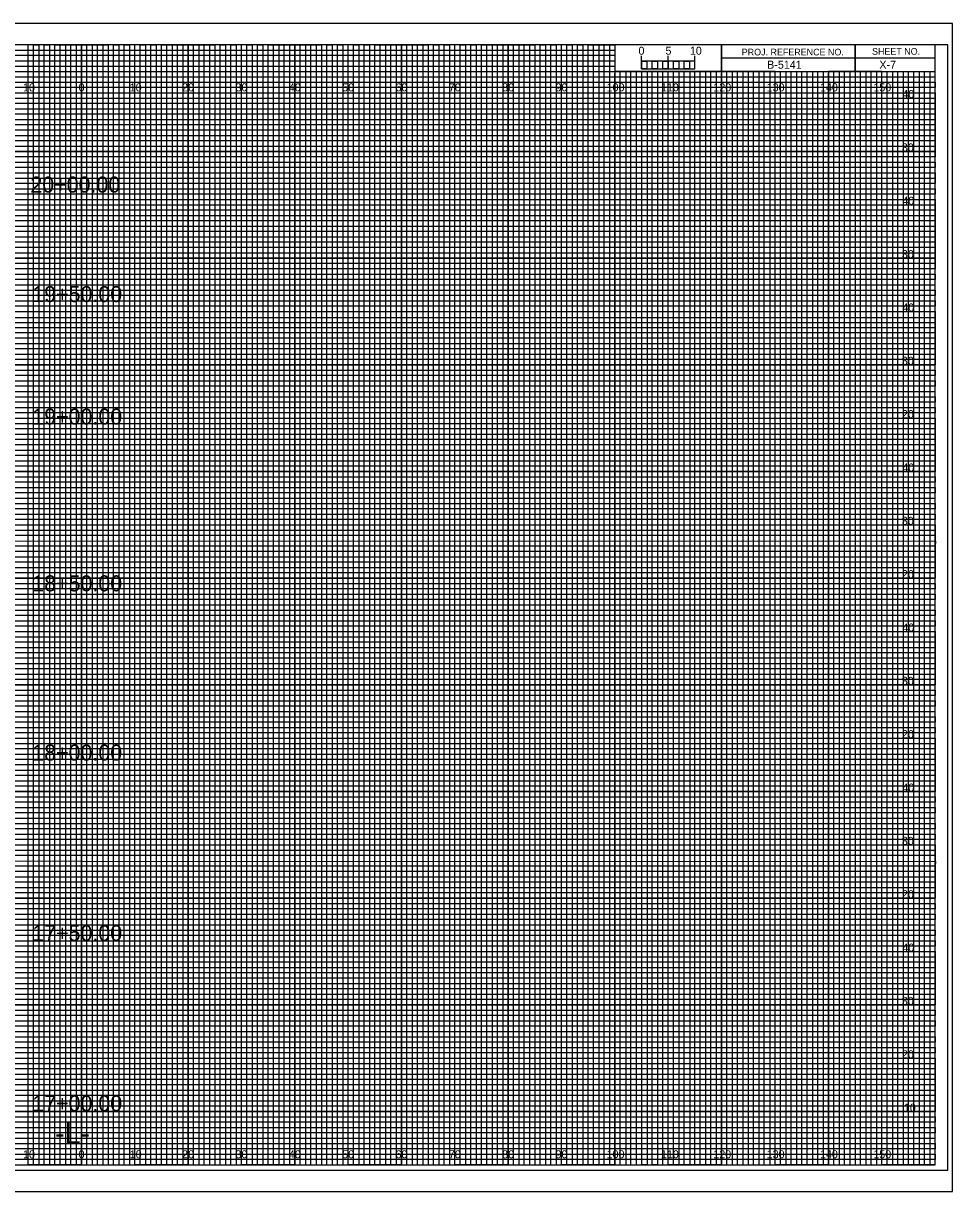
# Model space of a CAD drawing. Extents: x -13 to 323, y 435 to 654.
# Drawn here: x 149.1 to 323.3, y 435 to 654 of the extents above; entities that cross this region are included whole.
import ezdxf

# ---------------------------------------------------------------- set-up
doc = ezdxf.new("R2010")
doc.units = 0
for name, color, linetype in [('Exist Cross Section Cell', 7, 'Continuous'), ('Exist XS Center Line Elevation Label', 7, 'Continuous'), ('Exist XS Ground Line', 7, 'Continuous'), ('Prop XS DDE Slope Text', 7, 'Continuous'), ('Prop XS Earthwork Shape', 7, 'Continuous'), ('Prop XS EOT Tick Mark', 7, 'Continuous'), ('Prop XS Finish Grade', 7, 'Continuous'), ('Prop XS Finish Grade Earthwork', 7, 'Continuous'), ('Prop XS Finish Grade Paved Shoulder', 7, 'Continuous'), ('Prop XS Finish Grade Pavement', 7, 'Continuous'), ('Prop XS Label Text', 7, 'Continuous'), ('Prop XS Pvmt Edge Slope', 7, 'Continuous'), ('Prop XS SE Text', 7, 'Continuous'), ('Prop XS Side Slope Text', 7, 'Continuous'), ('Prop XS Subgrade Earthwork', 7, 'Continuous'), ('Sheet DOT Grid CELL', 7, 'Continuous'), ('Sheet Plot Border Inside CELL', 7, 'Continuous')]:
    doc.layers.add(name, color=color, linetype=linetype)

msp = doc.modelspace()

# ---------------------------------------------------------------- linework, layer by layer
at = {"layer": 'Exist XS Center Line Elevation Label'}
for points in [[(145, 440), (155, 440), (155, 650), (165, 650), (165, 440), (175, 440), (175, 650), (185, 650), (185, 440), (195, 440), (195, 650), (205, 650), (205, 440), (215, 440), (215, 650), (225, 650), (225, 440), (235, 440), (235, 650), (245, 650), (245, 440), (255, 440), (255, 650), (259.93, 650), (260, 650), (260, 645), (264.99, 645), (264.99, 440), (275, 440), (275, 645), (285, 645), (285, 440), (295, 440), (295, 645), (305, 645), (305, 440), (315, 440), (315, 645)], [(0, 645), (275, 645)], [(0, 625), (320, 625), (320, 635), (0, 635)], [(0, 605), (320, 605), (320, 615), (0, 615)], [(0, 585), (320, 585), (320, 595), (0, 595)], [(0, 565), (320, 565), (320, 575), (0, 575)], [(0, 545), (320, 545), (320, 555), (0, 555)], [(0, 525), (320, 525), (320, 535), (0, 535)], [(0, 505), (320, 505), (320, 515), (0, 515)], [(0, 485), (320, 485), (320, 495), (0, 495)], [(0, 465), (320, 465), (320, 475), (0, 475)], [(0, 445), (320, 445), (320, 455), (0, 455)]]:
    msp.add_lwpolyline(points, dxfattribs=at)
at = {"layer": 'Exist XS Ground Line'}
for p, q in [((150, 650), (140, 650)), ((150, 440), (150, 650)), ((170, 650), (160, 650)), ((160, 650), (160, 440)), ((170, 440), (170, 650)), ((190, 650), (180, 650)), ((180, 650), (180, 440)), ((190, 440), (190, 650)), ((210, 650), (200, 650)), ((200, 650), (200, 440)), ((210, 440), (210, 650)), ((230, 650), (220, 650)), ((220, 650), (220, 440)), ((230, 440), (230, 650)), ((250, 650), (240, 650)), ((240, 650), (240, 440)), ((250, 440), (250, 650)), ((260, 650), (260, 440)), ((270, 440), (270, 645)), ((290, 645), (280, 645)), ((280, 645), (280, 440)), ((290, 440), (290, 645)), ((310, 645), (300, 645)), ((300, 645), (300, 440)), ((310, 440), (310, 645)), ((160, 440), (150, 440)), ((180, 440), (170, 440)), ((200, 440), (190, 440)), ((220, 440), (210, 440)), ((240, 440), (230, 440)), ((260, 440), (250, 440)), ((280, 440), (270, 440)), ((300, 440), (290, 440)), ((320, 440), (310, 440)), ((320, 440), (320, 440))]:
    msp.add_line(p, q, dxfattribs=at)
for points in [[(0, 640), (320, 640), (320, 630), (0, 630)], [(0, 620), (320, 620), (320, 610), (0, 610)], [(0, 600), (320, 600), (320, 590), (0, 590)], [(0, 580), (320, 580), (320, 570), (0, 570)], [(0, 560), (320, 560), (320, 550), (0, 550)], [(0, 540), (320, 540), (320, 530), (0, 530)], [(0, 520), (320, 520), (320, 510), (0, 510)], [(0, 500), (320, 500), (320, 490), (0, 490)], [(0, 480), (320, 480), (320, 470), (0, 470)], [(0, 460), (320, 460), (320, 450), (0, 450)]]:
    msp.add_lwpolyline(points, dxfattribs=at)
at = {"layer": 'Prop XS DDE Slope Text'}
msp.add_lwpolyline([(-13.4, 435), (323.3, 435), (323.3, 654), (-13.4, 654)], close=True, dxfattribs=at)
at = {"layer": 'Prop XS Earthwork Shape'}
for p, q in [((0, 649), (260, 649)), ((260, 649), (260, 647.98)), ((260, 647.98), (0, 647.98)), ((0, 647), (260, 647)), ((260, 647), (260, 645.89)), ((260, 645.89), (0, 645.89)), ((0, 644), (320, 644))]:
    msp.add_line(p, q, dxfattribs=at)
for points in [[(0, 643), (270, 643), (320, 643), (320, 642), (0, 642)], [(0, 641), (320, 641), (320, 639), (0, 639)], [(0, 638), (320, 638), (320, 637), (0, 636.98)], [(0, 636), (320, 636), (320, 634), (0, 634)], [(0, 633), (320, 633), (320, 632), (0, 632)], [(0, 631), (320, 631), (320, 629), (0, 629)], [(0, 628), (320, 628), (320, 627), (0, 627)], [(0, 626), (320, 626), (320, 624), (0, 624)], [(0, 623), (320, 623), (320, 622), (0, 622)], [(0, 621), (320, 621), (320, 619), (0, 619)], [(0, 618), (320, 618), (320, 617), (0, 617)], [(0, 616), (320, 616), (320, 613.95), (320, 613), (320, 612), (0, 612)], [(0, 614), (320, 614), (320, 613), (0, 613)], [(0, 611), (320, 611), (320, 609), (0, 609.03)], [(0, 609.03), (320, 609), (320, 608), (0, 608)], [(0, 607), (320, 607), (320, 606), (0, 606)], [(0, 604), (320, 604), (320, 603), (0, 603)], [(0, 602), (320, 602), (320, 601), (0, 601)], [(-0.07, 598.89), (320, 598.89), (320, 597.88), (-0.07, 597.88)], [(0, 597), (320, 597), (320, 596), (0, 596)], [(0, 594), (320, 594), (320, 593), (0, 593)], [(0, 592), (320, 592), (320, 591), (0, 591)], [(0, 589), (320, 589), (320, 588), (0, 588)], [(0, 587), (320, 587), (320, 586), (0, 586)], [(0, 584), (320, 584), (320, 583), (0, 583)], [(0, 582), (320, 582), (320, 581), (0, 581)], [(0, 579), (320, 579), (319.99, 577.98), (0, 578)], [(0, 577), (320, 577), (320, 576), (0, 576)], [(0, 574), (320, 574), (320, 573), (0, 573)], [(0, 572), (320, 572), (320, 571), (0, 571)], [(0, 569), (320, 569), (320, 568), (0, 568)], [(0, 567), (320, 567), (320, 566), (0, 566)], [(0, 564), (320, 564), (320, 563), (0, 563)], [(0, 562), (320, 562), (320, 561), (0, 561)], [(0, 559), (320, 559), (320, 558), (0, 558)], [(0, 556.99), (320.07, 556.91), (320, 556), (0, 556)], [(0, 554), (320, 554), (320, 553), (0, 553)], [(0, 552), (320, 552), (320, 551), (0, 551)], [(0, 549), (320, 549), (320, 548), (0, 548)], [(0, 547), (320, 547), (320, 546), (0, 546)], [(0, 544), (320, 544), (320, 543), (0, 543)], [(0, 542), (320, 542), (320, 541), (0, 541)], [(0, 539), (320, 539), (320, 538), (0, 538)], [(0, 537), (320, 537), (320, 536), (0, 536)], [(0, 534), (320, 534), (320, 533), (0, 533)], [(0, 532), (320, 532), (320, 531), (0, 531)], [(0, 529), (320, 529), (320, 528), (0, 528)], [(0, 527), (320, 527), (320, 526), (0, 526)], [(0, 524), (320, 524), (320, 523), (0, 523)], [(0, 522), (320, 522), (320, 521), (0, 521)], [(0, 519), (320, 519), (319.99, 517.98), (0, 518)], [(0, 517), (320, 517), (320, 516), (0, 516)], [(0, 514), (320, 514), (320, 513), (0, 513)], [(0, 512), (320, 512), (320, 511), (0, 511)], [(0, 509), (320, 509), (320, 508), (0, 508)], [(0, 507), (320, 507), (320, 506), (0, 506)], [(0, 504), (320, 504), (320, 503), (0, 503)], [(0, 502), (320, 502), (320, 501), (0, 501)], [(0, 499), (320, 499), (320, 498), (0, 498)], [(0, 496.99), (320.07, 496.91), (320, 496), (0, 496)], [(0, 494), (320, 494), (320, 493), (0, 493)], [(0, 492), (320, 492), (320, 491), (0, 491)], [(0, 489), (320, 489), (320, 488), (0, 488)], [(0, 487), (320, 487), (320, 486), (0, 486)], [(0, 484), (320, 484), (320, 483), (0, 483)], [(0, 482), (320, 482), (320, 481), (0, 481)], [(0, 479), (320, 479), (320, 478), (0, 478)], [(0, 477), (320, 477), (320, 476), (0, 476)], [(0, 474), (320, 474), (320, 473), (0, 473)], [(0, 472), (320, 472), (320, 471), (0, 471)], [(0, 469), (320, 469), (320, 468), (0, 468)], [(0, 467), (320, 467), (320, 466), (0, 466)], [(0, 464), (320, 464), (320, 463), (0, 463)], [(0, 462), (320, 462), (320, 461), (0, 461)], [(0, 459), (320, 459), (320, 458), (0, 458)], [(0, 457), (320, 457), (320, 456), (0, 456)], [(0, 454), (320, 454), (320, 453), (0, 453)], [(0, 452), (320, 452), (320, 451), (0, 451)], [(0, 449), (320, 449), (320, 448), (0, 448)], [(0, 447), (320, 447), (320, 446), (0, 446)], [(0, 444), (320, 444), (320, 443), (0, 443)], [(0, 442), (320, 442), (320, 441), (0, 441)]]:
    msp.add_lwpolyline(points, dxfattribs=at)
at = {"layer": 'Prop XS Finish Grade Earthwork'}
for p, q in [((323.3, 654), (-13.4, 654)), ((-13.4, 435), (323.3, 435))]:
    msp.add_line(p, q, dxfattribs=at)
at = {"layer": 'Prop XS Label Text'}
for p, q in [((267, 645), (266.01, 645)), ((266.01, 645), (266.01, 440)), ((267, 440), (267, 645)), ((269, 645), (268, 645)), ((268, 645), (268, 440)), ((269, 440), (269, 645)), ((266.01, 440), (265, 440)), ((268, 440), (267, 440))]:
    msp.add_line(p, q, dxfattribs=at)
for points in [[(150, 440), (151, 440), (151, 650), (152, 650), (152, 440)], [(152, 440), (153, 440), (153, 650), (154, 650), (154, 440)], [(155, 440), (156, 440), (156, 650), (157, 650), (157, 440)], [(157, 440), (158, 440), (158, 650), (159, 650), (159, 440)], [(160, 440), (161, 440), (161, 650), (162, 650), (162, 440)], [(162, 440), (163, 440), (163, 650), (164, 650), (164, 440)], [(165, 440), (166, 440), (166, 650), (167, 650), (167, 440)], [(167, 440), (168, 440), (168, 650), (169, 650), (169, 440)], [(170, 440), (171, 440), (171, 650), (172, 650), (172, 440)], [(172, 440), (173, 440), (173, 650), (174, 650), (174, 440)], [(175, 440), (176, 440), (176, 650), (177, 650), (177, 440)], [(177, 440), (178, 440), (178, 650), (179, 650), (179, 440)], [(180, 440), (181, 440), (181, 650), (182, 650), (182, 440)], [(182, 440), (183, 440), (183, 650), (184, 650), (184, 440)], [(185, 440), (186, 440), (186, 650), (187, 650), (187, 440)], [(187, 440), (188, 440), (188, 650), (189, 650), (189, 440)], [(190, 440), (191, 440), (191, 650), (192, 650), (192, 440)], [(192, 440), (193, 440), (193, 650), (194, 650), (194, 440)], [(195, 440), (196, 440), (196, 650), (197, 650), (197, 440)], [(197, 440), (198, 440), (198, 650), (199, 650), (199, 440)], [(200, 440), (201, 440), (201, 650), (202, 650), (202, 440)], [(202, 440), (203, 440), (203, 650), (204, 650), (204, 440)], [(205, 440), (206, 440), (206, 650), (207, 650), (207, 440)], [(207, 440), (208, 440), (208, 650), (209, 650), (209, 440)], [(210, 440), (211, 440), (211, 650), (212, 650), (212, 440)], [(212, 440), (213, 440), (213, 650), (214, 650), (214, 440)], [(215, 440), (216, 440), (216, 650), (217, 650), (217, 440)], [(217, 440), (218, 440), (218, 650), (219, 650), (219, 440)], [(220, 440), (221, 440), (221, 650), (222, 650), (222, 440)], [(222, 440), (223, 440), (223, 650), (224, 650), (224, 440)], [(225, 440), (226, 440), (226, 650), (227, 650), (227, 440)], [(227, 440), (228, 440), (228, 650), (229, 650), (229, 440)], [(230, 440), (231, 440), (231, 650), (232, 650), (232, 440)], [(232, 440), (233, 440), (233, 650), (234, 650), (234, 440)], [(235, 440), (236, 440), (236, 650), (237, 650), (237, 440)], [(237, 440), (238, 440), (238, 650), (239, 650), (239, 440)], [(240, 440), (241, 440), (241, 650), (242, 650), (242, 440)], [(242, 440), (243, 440), (243, 650), (244, 650), (244, 440)], [(245, 440), (246, 440), (246, 650), (247, 650), (247, 440)], [(247, 440), (248, 440), (248, 650), (249, 650), (249, 440)], [(250, 440), (251, 440), (251, 650), (252, 650), (252, 440)], [(252, 440), (253, 440), (253, 650), (254, 650), (254, 440)], [(255, 440), (256, 440), (256, 650), (257, 650), (257, 440)], [(257, 440), (258, 440), (258, 650), (259, 650), (259, 440)], [(260, 440), (261, 440), (261, 645), (262.02, 645), (262.02, 440)], [(262, 440), (263, 440), (263, 645), (263.99, 645), (263.99, 440)], [(270, 440), (270.98, 440), (270.98, 645), (272, 645), (272, 440)], [(272, 440), (273, 440), (273, 645), (274.05, 645), (274.05, 440)], [(275, 440), (276, 440), (276, 645), (277, 645), (277, 440)], [(277, 440), (278, 440), (278, 645), (279, 645), (279, 440)], [(280, 440), (281, 440), (281, 645), (282, 645), (282, 440)], [(282, 440), (283, 440), (283, 645), (284, 645), (284, 440)], [(285, 440), (286, 440), (286, 645), (287, 645), (287, 440)], [(287, 440), (288, 440), (288, 645), (289, 645), (289, 440)], [(290, 440), (291, 440), (291, 645), (292, 645), (292, 440)], [(292, 440), (293, 440), (293, 645), (294, 645), (294, 440)], [(295, 440), (296, 440), (296, 645), (297, 645), (297, 440)], [(297, 440), (298, 440), (298, 645), (299, 645), (299, 440)], [(300, 440), (301, 440), (301, 645), (302, 645), (302, 440)], [(302, 440), (303, 440), (303, 645), (304, 645), (304, 440)], [(305, 440), (306, 440), (306, 645), (307, 645), (307, 440)], [(307, 440), (308, 440), (308, 645), (309, 645), (309, 440)], [(310, 440), (311, 440), (311, 645), (312, 645), (312, 440)], [(312, 440), (313, 440), (313, 645), (314, 645), (314, 440)], [(315, 440), (316, 440), (316, 645), (317, 645), (317, 440)], [(317, 440), (318, 440), (318, 645), (319, 645), (319, 440)]]:
    msp.add_lwpolyline(points, dxfattribs=at)
at = {"layer": 'Prop XS SE Text'}
for p, q in [((305, 650), (305, 645)), ((305, 645), (305, 650)), ((280, 647.5), (280, 645)), ((320, 647.49), (280, 647.49)), ((280, 645), (320, 645))]:
    msp.add_line(p, q, dxfattribs=at)
for points in [[(320, 650), (0, 650), (0, 440), (320, 440)], [(280, 650), (260, 650), (260, 645.03), (280, 645.03)], [(320, 650), (280, 650), (280, 645), (320, 645)]]:
    msp.add_lwpolyline(points, close=True, dxfattribs=at)
at = {"layer": 'Prop XS Side Slope Text'}
for p, q in [((265, 645.49), (265, 647.9)), ((265, 646.9), (265, 647.9)), ((270, 645.49), (270, 647.9)), ((275, 645.49), (275, 647.9)), ((275, 646.9), (275, 647.9))]:
    msp.add_line(p, q, dxfattribs=at)
for points in [[(275, 646.9), (265, 646.9), (265, 645.49), (275, 645.49)], [(265, 646.9), (266, 646.9), (266, 645.49), (265, 645.49)], [(267, 646.9), (268, 646.9), (268, 645.49), (267, 645.49)], [(269, 646.9), (270, 646.9), (270, 645.49), (269, 645.49)], [(271, 646.9), (272, 646.9), (272, 645.49), (271, 645.49)], [(273, 646.9), (274, 646.9), (274, 645.49), (273, 645.49)]]:
    msp.add_lwpolyline(points, close=True, dxfattribs=at)
at = {"layer": 'Sheet DOT Grid CELL'}
for p, q in [((150, 440), (150, 650)), ((160, 440), (160, 650)), ((170, 440), (170, 650)), ((180, 440), (180, 650)), ((190, 440), (190, 650)), ((200, 440), (200, 650)), ((210, 440), (210, 650)), ((220, 440), (220, 650)), ((230, 440), (230, 650)), ((240, 440), (240, 650)), ((250, 440), (250, 650)), ((260, 440), (260, 644.69)), ((270, 440), (270, 644.69)), ((280, 440), (280, 644.69)), ((290, 440), (290, 644.69)), ((300, 440), (300, 644.69)), ((310, 440), (310, 644.69)), ((0, 640), (320, 640)), ((0, 630), (320, 630)), ((0, 620), (320, 620)), ((0, 610), (320, 610)), ((0, 600), (320, 600)), ((0, 590), (320, 590)), ((0, 580), (320, 580)), ((0, 570), (320, 570)), ((0, 560), (320, 560)), ((0, 550), (320, 550)), ((0, 540), (320, 540)), ((0, 530), (320, 530)), ((0, 520), (320, 520)), ((0, 510), (320, 510)), ((0, 500), (320, 500)), ((0, 490), (320, 490)), ((0, 480), (320, 480)), ((0, 470), (320, 470)), ((0, 460), (320, 460)), ((0, 450), (320, 450))]:
    msp.add_line(p, q, dxfattribs=at)
at = {"layer": 'Sheet Plot Border Inside CELL'}
msp.add_lwpolyline([(-10.8, 439), (322.4, 439), (322.4, 650), (-10.8, 650)], close=True, dxfattribs=at)

# ---------------------------------------------------------------- texts
at = {"layer": 'Exist Cross Section Cell'}
for s, p in [('10', (149.04, 641.25)), ('0', (159.45, 641.25)), ('0', (159.45, 641.25)), ('10', (169.04, 641.25)), ('20', (178.86, 641.25)), ('30', (188.86, 641.25)), ('40', (198.86, 641.25)), ('50', (208.86, 641.25)), ('60', (218.86, 641.25)), ('70', (228.86, 641.25)), ('80', (238.86, 641.25)), ('90', (248.86, 641.25)), ('100', (258.44, 641.25)), ('110', (268.62, 641.25)), ('120', (278.44, 641.25)), ('130', (288.44, 641.25)), ('140', (298.44, 641.25)), ('150', (308.44, 641.25)), ('10', (149.04, 441.25)), ('0', (159.45, 441.25)), ('0', (159.45, 441.25)), ('10', (169.04, 441.25)), ('20', (178.86, 441.25)), ('30', (188.86, 441.25)), ('40', (198.86, 441.25)), ('50', (208.86, 441.25)), ('60', (218.86, 441.25)), ('70', (228.86, 441.25)), ('80', (238.86, 441.25)), ('90', (248.86, 441.25)), ('100', (258.44, 441.25)), ('110', (268.62, 441.25)), ('120', (278.44, 441.25)), ('130', (288.44, 441.25)), ('140', (298.44, 441.25)), ('150', (308.44, 441.25))]:
    msp.add_text(s, height=1.5, dxfattribs=at).set_placement(p)
at = {"layer": 'Prop XS EOT Tick Mark'}
msp.add_text('-L-', height=4, dxfattribs=at).set_placement((155.06, 444))
at = {"layer": 'Prop XS Finish Grade'}
for s, p in [('40', (313.87, 640)), ('30', (313.78, 630)), ('40', (313.87, 620)), ('30', (313.78, 610)), ('40', (313.87, 600)), ('30', (313.78, 590)), ('20', (313.8, 580)), ('40', (313.87, 570)), ('30', (313.78, 560)), ('20', (313.8, 550)), ('40', (313.87, 540)), ('30', (313.78, 530)), ('20', (313.8, 520)), ('40', (313.87, 510)), ('30', (313.78, 500)), ('20', (313.8, 490)), ('40', (313.87, 480)), ('30', (313.78, 470)), ('20', (313.8, 460)), ('10', (314.17, 450))]:
    msp.add_text(s, height=1.5, dxfattribs=at).set_placement(p)
at = {"layer": 'Prop XS Finish Grade Paved Shoulder'}
msp.add_text('X-7', height=1.5, dxfattribs=at).set_placement((309.57, 645.5))
at = {"layer": 'Prop XS Finish Grade Pavement'}
for s, p in [('5', (269.47, 648.12)), ('10', (274.04, 648.12))]:
    msp.add_text(s, height=1.5, dxfattribs=at).set_placement(p)
at = {"layer": 'Prop XS Pvmt Edge Slope'}
msp.add_text('B-5141', height=1.5, dxfattribs=at).set_placement((288.53, 645.5))
at = {"layer": 'Prop XS SE Text'}
for s, p in [('PROJ. REFERENCE NO.', (283.77, 647.99)), ('SHEET NO.', (308.19, 648.12))]:
    msp.add_text(s, height=1.25, dxfattribs=at).set_placement(p)
at = {"layer": 'Prop XS Side Slope Text'}
msp.add_text('0', height=1.5, dxfattribs=at).set_placement((264.41, 648.12))
at = {"layer": 'Prop XS Subgrade Earthwork'}
for s, p in [('20+00.00', (150.41, 622.28)), ('19+50.00', (150.77, 601.75)), ('19+00.00', (150.77, 578.79)), ('18+50.00', (150.77, 547.53)), ('18+00.00', (150.77, 515.8)), ('17+50.00', (150.77, 481.97)), ('17+00.00', (150.77, 450.05))]:
    msp.add_text(s, height=3, dxfattribs=at).set_placement(p)

doc.saveas('drawing.dxf')
